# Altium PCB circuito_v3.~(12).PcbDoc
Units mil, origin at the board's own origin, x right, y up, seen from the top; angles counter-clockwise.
Board outline 6000 x 4000 mil, 2 copper layers (Top Layer, Bottom Layer); 47 components, 32 nets, 112 pads, 0 vias.
Unrouted connection lines stored in the file: 62.
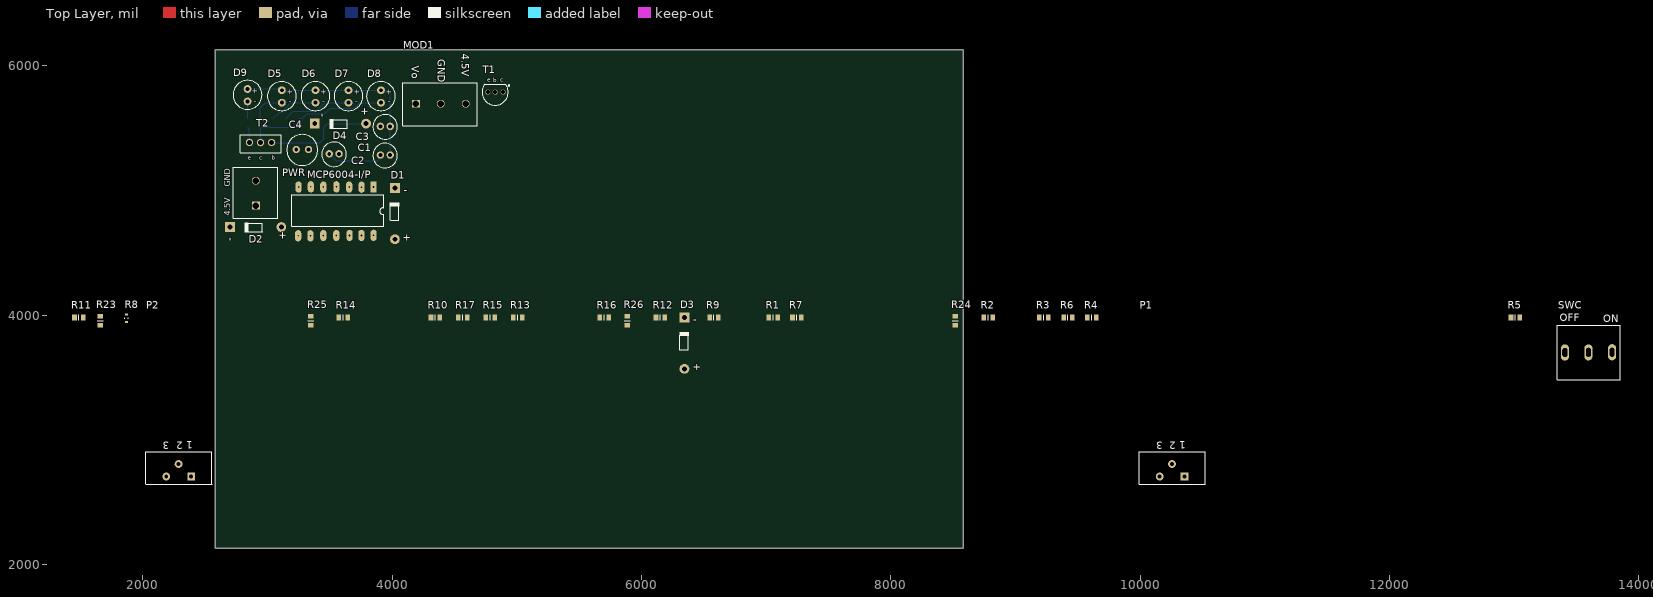
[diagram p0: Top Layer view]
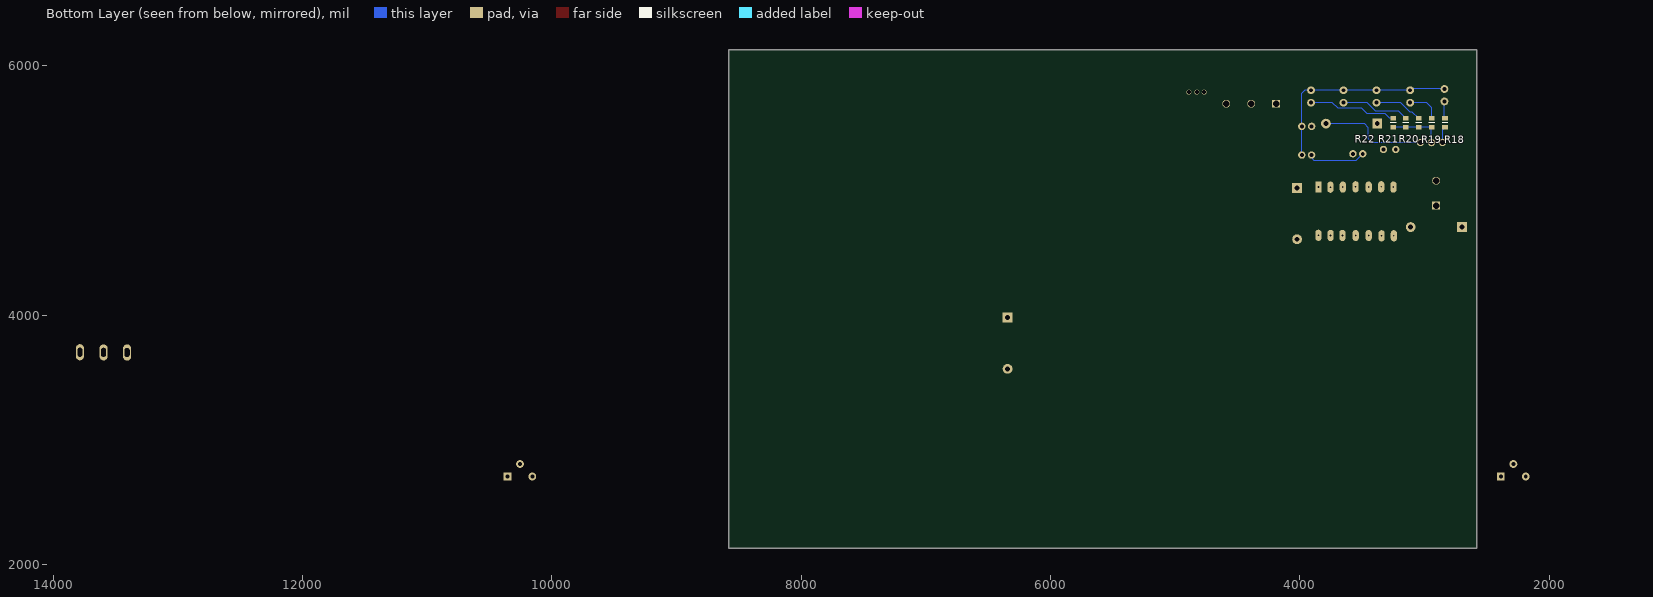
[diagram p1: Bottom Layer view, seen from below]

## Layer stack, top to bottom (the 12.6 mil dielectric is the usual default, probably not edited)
Top Layer: signal copper 1.4
Dielectric: dielectric 12.6, FR-4, Dk 4.8
Bottom Layer: signal copper 1.4

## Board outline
2580,2130 2580,6130 8580,6130 8580,2130

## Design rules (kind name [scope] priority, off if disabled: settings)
Clearance [All] p1: gap=10
FabricationTestPointUsage TestPointUsage [All] p1: valid=0 allowmultiple=FALSE
FabricationTestpoint Testpoint [All] p1: side=3 testpointundercomponent=TRUE minsize=40 maxsize=100 preferedsize=60 minholesize=0 maxholesize=40 preferedholesize=32 testpointgrid=1 allowsidetop=TRUE allowsidebottom=TRUE usegrid=TRUE gridtolerance=0.01
PolygonConnect [All] p1: connectstyle=Relief reliefconductorwidth=10 reliefentries=4 polygonreliefangle="90 Angle" airgapwidth=10
RoutingVias [All] p1: holewidth=28 width=50 viastyle="Through Hole" minholewidth=28 minwidth=50 maxholewidth=28 maxwidth=50
SilkToSolderMaskClearance SilkscreenOverComponentPads [IsPad] p1: minsilkscreentomaskgap=10 clearancetoexposedcopper=TRUE
SolderMaskExpansion [All] p1: expansion=4
Width [All] p1: maxlimit=10 minlimit=10 preferedwidth=10
25 further rules are at their usual default settings.

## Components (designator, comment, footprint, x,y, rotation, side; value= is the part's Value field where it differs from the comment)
C1 "Cap" "Condensador 5mm" 3945,5285 r0 top
C2 "Cap" "Condensador 5mm" 3535,5295 r0 top
C3 "Cap" "Condensador 5mm" 3945,5515 r0 top
C4 "Cap" "Condensador 6.3mm" 3280,5330 r0 top
D1 "BAT85" BAT85 4020,4820 r0 top
D2 "Diode BAT18" BAT85 2900,4705 r90 top
D3 "Diode BAT18" BAT85 6343.07,3780.75 r0 top
D4 "Diode BAT18" BAT85 3580,5535 r90 top
D5 "LED" LED 3115,5805 r270 top
D6 "LED" LED 3385,5805 r270 top
D7 "LED" LED 3650,5805 r270 top
D8 "LED" LED 3910,5805 r270 top
D9 "LED" "LED verde" 2840,5815 r270 top
MCP6004-I/P "MCP6004-I/P" MCP6004 3795,5035 r270 top
MOD1 "Conector" Conector 5615,5350 r270 top
P1 "Res Tap" POTENCIOMETRO 10258.07,2705.75 r90 top
P2 "Res Tap" POTENCIOMETRO 2288.07,2705.75 r90 top
PWR "Header 2" ALM 3560,5410 r90 top
R1 "Res1" "SMD 0805" 6783.07,4065.75 r0 top
R2 "Res1" "SMD 0805" 8508.07,4065.75 r0 top
R3 "Res1" "SMD 0805" 8953.07,4065.75 r0 top
R4 "Res1" "SMD 0805" 9338.07,4065.75 r0 top
R5 "Res1" "SMD 0805" 12738.07,4065.75 r0 top
R6 "Res1" "SMD 0805" 9148.07,4065.75 r0 top
R7 "Res1" "SMD 0805" 6973.07,4065.75 r0 top
R8 "Res1" "SMD 0603" 1868.07,3975.75 r0 top
R9 "Res1" "SMD 0805" 6308.07,4065.75 r0 top
R10 "Res1" "SMD 0805" 4073.07,4065.75 r0 top
R11 "Res1" "SMD 0805" 1213.07,4065.75 r0 top
R12 "Res1" "SMD 0805" 5878.07,4065.75 r0 top
R13 "Res1" "SMD 0805" 4733.07,4065.75 r0 top
R14 "Res1" "SMD 0805" 3333.07,4065.75 r0 top
R15 "Res1" "SMD 0805" 4513.07,4065.75 r0 top
R16 "Res1" "SMD 0805" 5428.07,4065.75 r0 top
R17 "Res1" "SMD 0805" 4293.07,4065.75 r0 top
R18 "Res3" "SMD 0805" 2920,5270 r90 bottom
R19 "Res3" "SMD 0805" 3025,5270 r90 bottom
R20 "Res3" "SMD 0805" 3130,5270 r90 bottom
R21 "Res3" "SMD 0805" 3235,5270 r90 bottom
R22 "Res3" "SMD 0805" 3335,5270 r90 bottom
R23 "Res1" "SMD 0805" 1573.07,3680.75 r90 top
R24 "Resistencia" "SMD 0805" 8433.07,3680.75 r90 top
R25 "Resistencia" "SMD 0805" 3263.07,3680.75 r90 top
R26 "Resistencia" "SMD 0805" 5803.07,3680.75 r90 top
SWC "Switch" switch 13488.07,3675.75 r0 top
T1 "2N3904" "T1 BC550C" 4420,8135 r90 top
T2 "QNPN" "T2 BD139" 2580,2850 r270 top

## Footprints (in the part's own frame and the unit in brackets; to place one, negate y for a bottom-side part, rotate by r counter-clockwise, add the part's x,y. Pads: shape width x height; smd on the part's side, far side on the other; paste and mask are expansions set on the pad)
ALM [mm]
  rect 1.6x1.6 hole 1.3: 1(-13.48,16.6)
  round 1.6 hole 1.3: 2(-8.4,16.6)
  silkscreen extent -16.07,12.12 -5.7,21.17, body extent -16.1,12.18 -4.94,21.17, height 15.2
BAT85 [mm]
  round 2 hole 1: 1(0.049,-5.353)
  rect 2x2 hole 1: 2(0.049,5.107)
  silkscreen extent -1,-1.53 0.97,2.1, body extent -1.02,-5.46 0.88,5.26, height 1.95
"Condensador 5mm" [mm]
  round 1.5 hole 0.8: 1(-1,0) 2(1,0)
  silkscreen extent -2.52,-2.6 2.47,2.4, body extent -2.45,-2.47 2.55,2.52, height 11
"Condensador 6.3mm" [mm]
  round 1.5 hole 0.8: 1(-1.25,0) 2(1.25,0)
  silkscreen extent -3.17,-3.25 3.12,3.05, body extent -3.22,-3.25 3.08,3.05, height 11.5
Conector [mm]
  rect 1.6x1.6 hole 1.3: 1(-8.811,-36.193)
  round 1.6 hole 1.3: 2(-8.811,-31.113) 3(-8.811,-26.033)
  silkscreen extent -13.13,-38.9 -4.35,-23.72, body extent -13.25,-38.87 -4.25,-23.63, height 15.2
LED [mm]
  round 1.6 hole 0.8: 1(0,0) 2(2.54,0)
  silkscreen extent -1.75,-2.95 4.15,2.95, body extent -1.68,-3.03 4.12,2.77, height 17.5
"LED verde" [mm]
  round 1.6 hole 0.8: 1(0,0) 2(2.54,0)
  silkscreen extent -1.75,-2.95 4.15,2.95, body extent -1.47,-3.12 4.23,2.87, height 20.86
MCP6004 [mil]
  rect 90x50 hole 14: 1(6.89,56.1)
  oval 90x50 hole 14: 2(7.87,-40.35) 3(6.89,-139.76) 4(4.92,-242.13) 5(6.89,-347.44) 6(4.92,-447.83) 7(6.89,-545.28) 8(397.64,-549.21) 9(397.64,-450.79) 10(395.67,-347.44) 11(395.67,-243.11) 12(394.69,-136.81) 13(394.69,-41.34) 14(393.7,56.1)
  silkscreen extent 70,-599 321,139, body extent -48,-623 452,147, height 181
POTENCIOMETRO [mm]
  rect 1.6x1.6 hole 0.8: 1(0.008,-2.535)
  round 1.6 hole 0.8: 2(2.548,0.025) 3(0.008,2.545)
  silkscreen extent -1.58,-6.78 5.07,6.75, body extent -4.59,-6.77 33.45,6.77, height 14.1
"SMD 0603" [mm]
  rect 0.64x0.44 smd mask+0.26: 1(0.018,-0.76) 2(0.018,0.74)
  silkscreen extent -0.33,-0.15 0.35,0.13, body extent -0.4,-0.9 0.4,0.8, height 0.56
"SMD 0805" [mm]
  rect 0.94x1.14 smd mask+0.26: 1(6.062,-2.136) 2(7.862,-2.136)
  silkscreen extent 6.96,-2.74 6.96,-1.54, body extent 6.08,-2.77 8.08,-1.52, height 0.78
switch [mil]
  oval 65x130 hole 39.37 slot 70.87 at 90 deg: 1(-79,25) 2(109.96,26) 3(298.94,27)
  silkscreen extent -139,-193 365,243, body extent -69,-61 250,136, height 720
"T1 BC550C" [mm]
  round 1 hole 0.8: 1(-59.575,-11.95) 2(-59.571,-10.328) 3(-59.575,-8.825)
  silkscreen extent -62.23,-13.28 -57.92,-7.67, body extent -61.73,-12.63 -58.1,-7.87, height 4.92
"T2 BD139" [mm]
  round 1.5 hole 1: 1(-64.425,6.992) 2(-64.389,9.246) 3(-64.4,11.5)
  silkscreen extent -65.95,5.07 -62.3,13.5, body extent -65.4,5.4 -62.7,13.2, height 13.6

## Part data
C1 C2 C3 C4: "Capacitor"
D1: library part "Diode BAT18", "Low-Loss RF Switching Diode"
D2 D3 D4: "Low-Loss RF Switching Diode"
D5 D6 D7 D8 D9: library part LED2, "Typical RED, GREEN, YELLOW, AMBER GaAs LED"
MCP6004-I/P: "DIP Switch, 7 Position, SPST"
MOD1: library part "Header 3", "Header, 3-Pin"
P1 P2: "Tapped Resistor"
PWR: "Header, 2-Pin"
R1 R2 R3 R4 R5 R6 R7 R8 R9 R10 R11 R12 R13 R14 R15 R16 R17 R18 R19 R20 R21 R22 R23 R24 R25 R26: "Resistor"
SWC: library part Conmutador
T1: "NPN General Purpose Amplifier"
T2: "NPN Bipolar Transistor"

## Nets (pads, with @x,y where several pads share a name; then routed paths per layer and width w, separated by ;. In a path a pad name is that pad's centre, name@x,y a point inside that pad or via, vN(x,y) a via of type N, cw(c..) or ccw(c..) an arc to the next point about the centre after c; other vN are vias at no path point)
"4.5 V": C1.2 C3.2 C4.2 D5.1 D6.1 D7.1 D8.1 D9.1 MCP6004-I/P.4 MOD1.3 P1.3 R5.2 R10.2 R13.2 R26.2 SWC.2 | length 1654.2
  Bottom Layer w10: D9.1 3105,5815 D5.1 D6.1 D7.1 D8.1 3960,5805 3984.37,5780.63 C3.2 C1.2
GND: C1.1 C2.1 MCP6004-I/P.11 MOD1.2 P1.1 PWR.2 R11.1 R17.2 R18.1 R25.2 SWC.1 T1.3 T2.1 | length 594.7
  Bottom Layer w10: R18.1 2855.28,5489.29 T2.1 ; C2.1 3550,5240.63 3884.37,5240.63 3905.63,5261.89 C1.1
NetD1_3: D1.2 R4.2
NetD2_1: D2.1 MCP6004-I/P.14
NetD3_1: D3.1 R12.1
NetD4_1: D4.1 R16.1 R17.1 T2.3 | length 873.5
  Bottom Layer w10: T2.3 3420.43,5385.43 3450,5415 3450,5505 3480,5535 3788.82,5535 D4.1
NetD5_2: D5.2 R19.2 | length 276.7
  Bottom Layer w10: R19.2 2940.91,5665.91 2980,5705 D5.2
NetD6_2: D6.2 R20.2 | length 391.1
  Bottom Layer w10: R20.2 3096.38,5630 3115,5630 3190,5705 D6.2
NetD7_2: D7.2 R21.2 | length 551.1
  Bottom Layer w10: R21.2 3206.38,5635 3390,5635 3460,5705 D7.2
NetD8_2: D8.2 R22.2 | length 711.1
  Bottom Layer w10: R22.2 3279.53,5579.53 3315,5615 3460,5615 3503.5,5658.5 3693.5,5658.5 3740,5705 D8.2
NetD9_2: D9.2 R18.2 | length 137.2
  Bottom Layer w10: R18.2 2840,5583.62 D9.2
NetMOD1_1: MOD1.1 R1.1 R9.2
NetP2_1: P2.2 P2.3 R10.1
NetPWR_1: PWR.1 SWC.3
NetR6_1: R6.1 R24.2
NetR7_2: R7.2 T1.2
NetR8_1: R8.1 R23.2
NetR14_2: R14.2 R25.1
NetR15_2: R15.2 R26.1
NetR19_1: R19.1 R20.1 R21.1 R22.1 T2.2 | length 434.9
  Bottom Layer w10: T2.2 2944.02,5505.55 R19.1 R20.1 R21.1 R22.1
NetR24_1: R24.1 T1.1
VA+: C2.2 MCP6004-I/P.3 P1.2
VA-: MCP6004-I/P.2 R1.2 R2.1
VB+: MCP6004-I/P.5 R5.1 R6.2 R8.2
VB-: C3.1 D2.2 MCP6004-I/P.6 R3.2 R4.1
VC+: MCP6004-I/P.10 R14.1 R15.1
VC-: C4.1 MCP6004-I/P.9 R12.2 R13.1
VD+: MCP6004-I/P.12 P2.1 R11.2
VD-: MCP6004-I/P.13 R9.1
VOUTA: MCP6004-I/P.1 R2.2 R3.1 R7.1
VOUTB: D1.1 D3.2 MCP6004-I/P.7 R16.2 R23.1
VOUTC: D4.2 MCP6004-I/P.8

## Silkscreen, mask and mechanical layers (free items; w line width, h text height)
Mechanical 16:
  drawing of 1874 lines, arcs and shapes, not listed
  text "1" at 1427,7465 h70
  text "2" at 4287,7465 h70
  text "3" at 7167,7465 h70
  text "4" at 10037,7465 h70
  text "A" at 75,6559 h70
  text "A" at 11375,6559 h70
  text "B" at 75,4667 h70
  text "B" at 11375,4667 h70
  text "C" at 4158.07,3082.75 h70
  text "C" at 75,2757 h70
  text "ENGINEER:" at 6850,1300 h45
  text "TITLE:" at 8350,1300 h45
  text "PCB DESIGNER:" at 6850,1005 h45
  text "D" at 75,867 h70
  text "D" at 11375,867 h70
  text "DATE:" at 6850,700 h45
  text "PART NO.:" at 8350,700 h45
  text "REV:" at 10450,700 h45
  text "Altium Limited" at 5550,600 h70
  text ".PRINT_DATE" at 6900,580 h70
  text "12a Rodborough Rd" at 5550,500 h70
  text "Frenchs Forest" at 5550,400 h70
  text "FILE NAME:" at 6850,400 h45
  text "DWG NO:" at 8350,400 h45
  text "SCALE:" at 10450,400 h45
  text "NSW 2086" at 5550,300 h70
  text ".PCB_FILE_NAME_NO_PATH" at 6900,280 h70
  text "1" at 1427,65 h70
  text "2" at 4287,65 h70
  text "3" at 7167,65 h70
  text "4" at 10037,65 h70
